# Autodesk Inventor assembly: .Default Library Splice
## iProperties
Part Number: .Default Library Splice
Material: Default
Description: Default Library Splice
ParentFileIdentifier: 5|1|0|0|108|1|0|0|80|0|65|0|84|0|72|0|83|0|59|0|67|0|58|0|92|0|86|0|97|0|117|0|108|0|116|0|32|0|87|0|111|0|114|0|107|0|115|0|112|0|97|0|99|0|101|0|92|0|69|0|110
Created: 2009-02
Part Number: 100500.Harness1
Document SubType Name: Assembly
Designer: Autodesk
HarnessSettings: <HarnessSettings><Defaults><Segments><Diameter value="0.200 in" fromwires="True"/><Offset value="0.100 in"/><ColorStyle value="Blue"/><RoundUp value=""/><BendRa
Author: Autodesk
